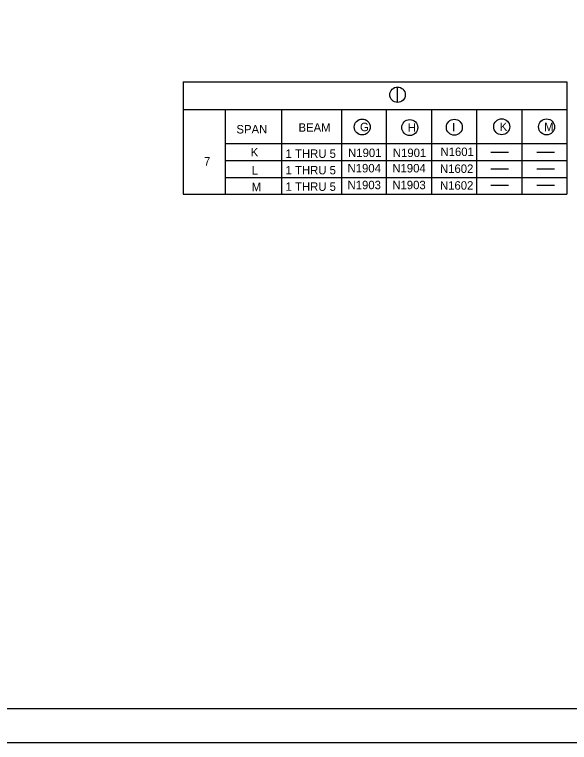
# Model space of a CAD drawing. Extents: x -50.5 to -14.4, y -5.1 to 16.9.
# Drawn here: x -36.11 to -27.92, y -5.07 to 5.69 of the extents above; entities that cross this region are included whole.
import ezdxf

# ---------------------------------------------------------------- set-up
doc = ezdxf.new("R2010")
doc.units = 0
for name, color, linetype in [('BR_AUTO DIMENSION', 7, 'Continuous'), ('BR_BORDER LINES', 7, 'Continuous'), ('BR_TABLE LINES', 7, 'Continuous'), ('BR_TEXT', 7, 'Continuous'), ('Level 31', 7, 'Continuous')]:
    doc.layers.add(name, color=color, linetype=linetype)

msp = doc.modelspace()

# ---------------------------------------------------------------- linework, layer by layer
at = {"layer": 'BR_AUTO DIMENSION'}
msp.add_line((-30.461, 4.387), (-30.461, 4.614), dxfattribs=at)
msp.add_circle((-30.461, 4.501), 0.114, dxfattribs=at)
at = {"layer": 'BR_BORDER LINES'}
for p, q in [((-33.626, 4.692), (-33.626, 3.031)), ((-33.626, 4.692), (-27.963, 4.692)), ((-27.963, 4.692), (-27.963, 3.031)), ((-33.626, 4.281), (-27.963, 4.281)), ((-33.626, 3.031), (-27.963, 3.031)), ((-48.685, -4.566), (-15.019, -4.566))]:
    msp.add_line(p, q, dxfattribs=at)
at = {"layer": 'BR_TABLE LINES'}
for p, q in [((-33.005, 4.281), (-33.005, 3.031)), ((-32.174, 4.281), (-32.174, 3.031)), ((-31.287, 4.281), (-31.287, 3.031)), ((-31.287, 4.281), (-31.287, 3.031)), ((-30.627, 4.281), (-30.627, 3.031)), ((-29.961, 4.281), (-29.961, 3.031)), ((-29.295, 4.281), (-29.295, 3.031)), ((-28.629, 4.281), (-28.629, 3.031)), ((-28.629, 4.281), (-28.629, 3.031)), ((-33.005, 3.781), (-27.963, 3.781)), ((-33.005, 3.531), (-27.963, 3.531)), ((-33.005, 3.281), (-27.963, 3.281)), ((-33.626, 3.031), (-27.963, 3.031)), ((-32.174, 3.031), (-27.963, 3.031))]:
    msp.add_line(p, q, dxfattribs=at)
at = {"layer": 'BR_TEXT'}
for p, q in [((-29.086, 3.654), (-28.825, 3.654)), ((-28.406, 3.654), (-28.145, 3.654)), ((-29.086, 3.405), (-28.825, 3.405)), ((-28.406, 3.405), (-28.145, 3.405)), ((-29.086, 3.165), (-28.825, 3.165)), ((-28.406, 3.165), (-28.145, 3.165))]:
    msp.add_line(p, q, dxfattribs=at)
for centre in [(-30.983, 4.025), (-30.281, 4.017), (-29.623, 4.021), (-28.924, 4.029), (-28.261, 4.026)]:
    msp.add_circle(centre, 0.118, dxfattribs=at)
at = {"layer": 'Level 31'}
msp.add_lwpolyline([(-50.519, -5.066), (-14.519, -5.066), (-14.519, 16.934), (-50.519, 16.934)], close=True, dxfattribs=at)

# ---------------------------------------------------------------- texts
at = {"layer": 'BR_TEXT'}
for s, p in [('G', (-31.015, 3.963)), ('K', (-28.953, 3.966)), ('M', (-28.297, 3.963)), ('SPAN', (-32.839, 3.929)), ('BEAM', (-31.923, 3.955)), ('H', (-30.31, 3.954)), ('I', (-29.656, 3.959)), ('K', (-32.628, 3.59)), ('7', (-33.318, 3.456)), ('L', (-32.614, 3.322)), ('M', (-32.614, 3.077))]:
    msp.add_text(s, height=0.125, rotation=360, dxfattribs=at).set_placement(p)
for s, p in [('1 THRU 5', (-32.114, 3.569)), ('N1901', (-31.191, 3.581)), ('N1901', (-30.53, 3.581)), ('N1601', (-29.827, 3.596)), ('1 THRU 5', (-32.114, 3.325)), ('N1904', (-31.199, 3.354)), ('N1904', (-30.538, 3.354)), ('N1602', (-29.835, 3.347)), ('N1903', (-31.199, 3.106)), ('N1903', (-30.538, 3.106)), ('N1602', (-29.835, 3.099)), ('1 THRU 5', (-32.114, 3.082))]:
    msp.add_text(s, height=0.125, dxfattribs=at).set_placement(p)

doc.saveas('drawing.dxf')
